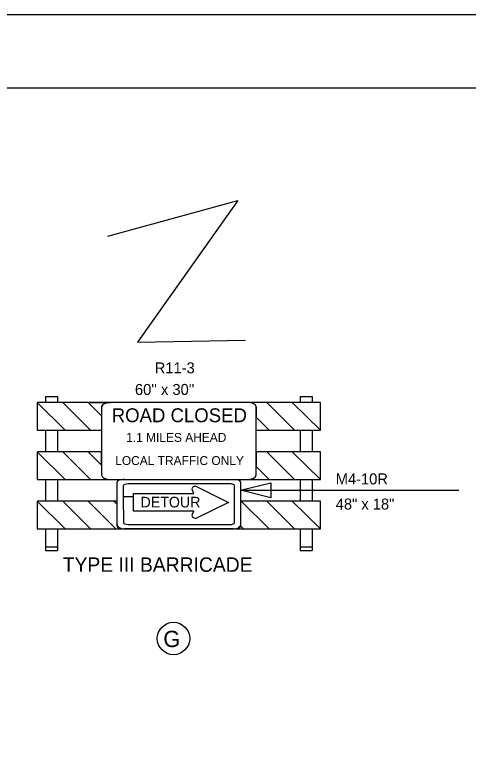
# Model space of a CAD drawing. Extents: x 2157572 to 5059327, y 715220 to 1674494.
# Drawn here: x 2160046 to 2161279, y 729076 to 731089 of the extents above; entities that cross this region are included whole.
import ezdxf

# ---------------------------------------------------------------- set-up
doc = ezdxf.new("R2010")
doc.units = 0
for name, color, linetype in [('Exist Cultural Church Label', 7, 'Continuous'), ('Exist Hydrographic Creek Double Shore Label', 7, 'Continuous'), ('Exist Road Secondary Type 51 Divided Label', 7, 'Continuous'), ('Map Preparation Border Control Points', 7, 'Continuous'), ('Map Preparation County Base Legend Highway Garage or Maintenance Office', 7, 'Continuous'), ('Map Preparation County North Arrow White Shapes', 7, 'Continuous')]:
    doc.layers.add(name, color=color, linetype=linetype)

msp = doc.modelspace()

# ---------------------------------------------------------------- linework, layer by layer
at = {"layer": 'Exist Cultural Church Label'}
msp.add_circle((2160477.3, 729390.6), 44.1, dxfattribs=at)
at = {"layer": 'Exist Hydrographic Creek Double Shore Label'}
msp.add_line((2160379.2, 730197.2), (2160673.5, 730202.5), dxfattribs=at)
msp.add_lwpolyline([(2160298.9, 730486.4), (2160652.1, 730582.8), (2160379.2, 730197.2)], dxfattribs=at)
at = {"layer": 'Exist Road Secondary Type 51 Divided Label'}
msp.add_lwpolyline([(2157571.9, 722288.7), (2171075.9, 722288.7), (2171075.9, 731088.6), (2157571.9, 731088.6)], close=True, dxfattribs=at)
at = {"layer": 'Map Preparation Border Control Points'}
for p, q in [((2160129.4, 730049.9), (2160162.1, 730049.9)), ((2160129.4, 730049.9), (2160129.4, 730033.5)), ((2160162.1, 730049.9), (2160162.1, 730033.5)), ((2160821.5, 730049.9), (2160854.2, 730049.9)), ((2160821.5, 730049.9), (2160821.5, 730033.5)), ((2160854.2, 730049.9), (2160854.2, 730033.5)), ((2160877.1, 730033.5), (2160106.5, 730033.5)), ((2160106.5, 730033.5), (2160106.5, 729958)), ((2160175.9, 730033.5), (2160106.5, 730033.5)), ((2160106.5, 730033.5), (2160182.1, 729958)), ((2160251.4, 729958), (2160175.9, 730033.5)), ((2160281.8, 729996.9), (2160245.2, 730033.5)), ((2160245.2, 730033.5), (2160306.2, 730033.5)), ((2160730.9, 730033.5), (2160677.3, 730033.5)), ((2160806.5, 729958), (2160730.9, 730033.5)), ((2160877.1, 730033.5), (2160800.3, 730033.5)), ((2160800.3, 730033.5), (2160877.1, 729958)), ((2160877.1, 729958), (2160877.1, 730033.5)), ((2160877.1, 729958), (2160877.1, 730033.5)), ((2160281.8, 730021.3), (2160281.8, 729996.9)), ((2160281.8, 730021.3), (2160281.8, 730021.3)), ((2160701.8, 730021.3), (2160701.8, 729993.3)), ((2160701.8, 729993.3), (2160737.1, 729958)), ((2160106.5, 729958), (2160281.8, 729958)), ((2160129.4, 729958), (2160129.4, 729899.1)), ((2160162.1, 729958), (2160162.1, 729899.1)), ((2160182.1, 729958), (2160251.4, 729958)), ((2160701.8, 729958), (2160877.1, 729958)), ((2160737.1, 729958), (2160806.5, 729958)), ((2160821.5, 729958), (2160821.5, 729899.1)), ((2160854.2, 729958), (2160854.2, 729899.1)), ((2160106.5, 729899.1), (2160106.5, 729823.5)), ((2160175.9, 729899.1), (2160106.5, 729899.1)), ((2160106.5, 729899.1), (2160182.1, 729823.5)), ((2160281.8, 729899.1), (2160106.5, 729899.1)), ((2160251.4, 729823.5), (2160175.9, 729899.1)), ((2160281.8, 729899.1), (2160245.2, 729899.1)), ((2160245.2, 729899.1), (2160281.8, 729862.4)), ((2160281.8, 729862.4), (2160281.8, 729899.1)), ((2160877.1, 729899.1), (2160701.8, 729899.1)), ((2160730.9, 729899.1), (2160701.8, 729899.1)), ((2160806.5, 729823.5), (2160730.9, 729899.1)), ((2160877.1, 729899.1), (2160800.3, 729899.1)), ((2160800.3, 729899.1), (2160877.1, 729823.5)), ((2160877.1, 729823.5), (2160877.1, 729899.1)), ((2160877.1, 729823.5), (2160877.1, 729899.1)), ((2160106.5, 729823.5), (2160877.1, 729823.5)), ((2160129.4, 729823.5), (2160129.4, 729764.6)), ((2160162.1, 729823.5), (2160162.1, 729764.6)), ((2160182.1, 729823.5), (2160251.4, 729823.5)), ((2160340.7, 729807.3), (2160340.7, 729777.5)), ((2160631, 729811.4), (2160353.5, 729811.7)), ((2160643.4, 729705.4), (2160643.4, 729807.3)), ((2160737.1, 729823.5), (2160806.5, 729823.5)), ((2160821.5, 729823.5), (2160821.5, 729764.6)), ((2160854.2, 729823.5), (2160854.2, 729764.6)), ((2160368.6, 729777.5), (2160368.6, 729785.5)), ((2160368.6, 729785.5), (2160532.9, 729785.5)), ((2160532.9, 729785.5), (2160528, 729796.4)), ((2160541.7, 729803.8), (2160626.7, 729761.2)), ((2160659.8, 729794.1), (2161253.2, 729794.1)), ((2160340.7, 729777.5), (2160368.6, 729777.5)), ((2160368.6, 729776.6), (2160340.7, 729776.6)), ((2160340.7, 729776.6), (2160341, 729705.4)), ((2160368.6, 729737.6), (2160368.6, 729776.6)), ((2160175.9, 729764.6), (2160106.5, 729764.6)), ((2160106.5, 729764.6), (2160182.1, 729689.1)), ((2160106.5, 729764.6), (2160106.5, 729689.1)), ((2160323.8, 729764.6), (2160106.5, 729764.6)), ((2160251.4, 729689.1), (2160175.9, 729764.6)), ((2160245.2, 729764.6), (2160320.8, 729689.1)), ((2160314.6, 729764.6), (2160245.2, 729764.6)), ((2160323.8, 729755.4), (2160314.6, 729764.6)), ((2160323.8, 729701.3), (2160323.8, 729755.4)), ((2160626.7, 729761.2), (2160541.7, 729719.6)), ((2160877.1, 729764.6), (2160659.8, 729764.6)), ((2160730.9, 729764.6), (2160661.6, 729764.6)), ((2160661.6, 729764.6), (2160737.1, 729689.1)), ((2160806.5, 729689.1), (2160730.9, 729764.6)), ((2160877.1, 729764.6), (2160800.3, 729764.6)), ((2160800.3, 729764.6), (2160877.1, 729689.1)), ((2160877.1, 729689.1), (2160877.1, 729764.6)), ((2160877.1, 729689.1), (2160877.1, 729764.6)), ((2160532.8, 729737.6), (2160368.6, 729737.6)), ((2160528, 729727), (2160532.8, 729737.6)), ((2160106.5, 729689.1), (2160877.1, 729689.1)), ((2160129.4, 729689.1), (2160129.4, 729630.2)), ((2160162.1, 729689.1), (2160162.1, 729630.2)), ((2160182.1, 729689.1), (2160251.4, 729689.1)), ((2160320.8, 729689.1), (2160343.3, 729689.1)), ((2160640.2, 729689.1), (2160343.4, 729689.1)), ((2160353.8, 729701.2), (2160631, 729701.2)), ((2160640.2, 729689.1), (2160667.8, 729689.1)), ((2160667.8, 729689.1), (2160659, 729697.9)), ((2160737.1, 729689.1), (2160806.5, 729689.1)), ((2160821.5, 729689.1), (2160821.5, 729630.2)), ((2160854.2, 729689.1), (2160854.2, 729630.2)), ((2160129.4, 729640), (2160162.1, 729640)), ((2160129.4, 729630.2), (2160162.1, 729630.2)), ((2160821.5, 729640), (2160854.2, 729640)), ((2160821.5, 729630.2), (2160854.2, 729630.2))]:
    msp.add_line(p, q, dxfattribs=at)
for points in [[(2160677.3, 730033.5), (2160306.3, 730033.5)], [(2160281.8, 730021.3), (2160281.8, 729835.8)], [(2160701.8, 729835.8), (2160701.8, 730021.3)], [(2160701.8, 729899.1), (2160701.8, 729858.8), (2160737.1, 729823.5)], [(2160306.3, 729823.5), (2160677.3, 729823.5)], [(2160323.8, 729696.4), (2160323.8, 729816.2)], [(2160343.4, 729823.5), (2160640.2, 729823.5)], [(2160659.8, 729816.2), (2160659.8, 729696.4)]]:
    msp.add_lwpolyline(points, dxfattribs=at)
msp.add_lwpolyline([(2160741.6, 729773.7), (2160659.8, 729794.1), (2160741.6, 729814.6)], close=True, dxfattribs=at)
msp.add_lwpolyline([(2160741.6, 729773.7), (2160659.8, 729794.1), (2160741.6, 729814.6)], close=True, dxfattribs=at)
for centre, major_axis, ratio, start_param, end_param in [((2160306.3, 730021.3), (-24.5, 0), 0.5, 4.712304, 6.283185), ((2160306.3, 730021.3), (-24.5, 0), 0.5, 4.712389, 6.283185), ((2160677.3, 730021.3), (24.5, 0), 0.5, 0, 1.571024), ((2160677.3, 730021.3), (24.5, 0), 0.5, 0, 1.571024), ((2160306.3, 729835.8), (24.5, 0), 0.5, 3.141593, 4.712389), ((2160677.3, 729835.8), (24.5, 0), 0.5, 4.712389, 6.283185), ((2160343.4, 729816.2), (-19.6, 0), 0.375009, 4.712162, 6.283185), ((2160353.6, 729807.3), (-12.6, 0), 0.337508, 4.712581, 6.283188), ((2160630.8, 729807.3), (12.6, 0), 0.337508, 6.283178, 7.854173), ((2160640.2, 729816.2), (19.6, 0), 0.375009, 0, 1.570796), ((2160536.5, 729798.1), (9, 0), 0.720018, 0.96961, 3.452569), ((2160536.5, 729724.9), (9, 0), 0.720018, 2.830617, 5.313577), ((2160353.8, 729705.4), (-12.6, 0), 0.337508, 0.000003, 1.57061), ((2160631, 729705.4), (12.6, 0), 0.337508, 4.712203, 6.283178), ((2160343.4, 729701.3), (19.6, 0), 0.625, 3.141593, 4.712389), ((2160343.4, 729696.4), (-19.6, 0), 0.375009, 0, 1.570796), ((2160640.2, 729701.3), (19.6, 0), 0.625, 4.712497, 5.996053), ((2160640.2, 729696.4), (-19.6, 0), 0.375009, 1.570796, 3.141593)]:
    msp.add_ellipse(centre, major_axis=major_axis, ratio=ratio, start_param=start_param, end_param=end_param, dxfattribs=at)
at = {"layer": 'Map Preparation County Base Legend Highway Garage or Maintenance Office'}
msp.add_circle((2160477.3, 729390.6), 44.1, dxfattribs=at)
at = {"layer": 'Map Preparation County North Arrow White Shapes'}
msp.add_lwpolyline([(2170875.9, 730888.7), (2158875.9, 730888.7), (2158875.9, 722488.7), (2170875.9, 722488.7)], close=True, dxfattribs=at)

# ---------------------------------------------------------------- texts
at = {"layer": 'Exist Cultural Church Label'}
msp.add_text('G', height=44.3, dxfattribs=at).set_placement((2160449.5, 729367.3))
at = {"layer": 'Map Preparation Border Control Points'}
for s, height, p in [('R11-3', 29.88, (2160426.1, 730112.5)), ("60'' x 30''", 29.88, (2160372.4, 730053.7)), ('ROAD CLOSED', 37.785, (2160309.1, 729979.5)), ('1.1 MILES AHEAD', 24.287, (2160348.5, 729925.9)), ('LOCAL TRAFFIC ONLY', 24.287, (2160318.7, 729862.9)), ('M4-10R', 29.88, (2160918.5, 729810.2)), ('DETOUR', 28.88, (2160387.4, 729747.5)), ('48" x 18"', 29.88, (2160918.5, 729741.8)), ('TYPE III BARRICADE', 39.25, (2160176, 729572.2))]:
    msp.add_text(s, height=height, dxfattribs=at).set_placement(p)

doc.saveas('drawing.dxf')
